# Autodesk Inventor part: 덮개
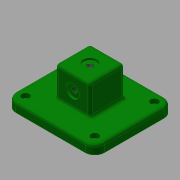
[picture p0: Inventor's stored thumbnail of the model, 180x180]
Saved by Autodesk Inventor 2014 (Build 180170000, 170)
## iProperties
Created: 2017-08
Part Number: 덮개
Material: 알루미늄 6061
Document SubType Name: Modeling
Designer: mduedu
Density: 1 g/cm^3
Appearance: Dark Green
Author: mduedu
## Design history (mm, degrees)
sketch "스케치1"
  geometry: L1 (46, -41)-(-46, -41); L2 (-46, -41)-(-46, 41); L3 (-46, 41)-(46, 41); L4 (46, 41)-(46, -41); 1 further point
  constraints: 8 end point, 2 parallel, 1 horizontal, 1 perpendicular
  dimensions: "d0" = 92 distance of L2.end L3.end; "d2" = 82 distance of L1.end L2.end; "d3" = 41 distance from line of L3 point (0, 0) (= 0.5 x d2); "d4" = 46 distance from line of point (0, 0) L4 (= 0.5 x d0)
extrude "돌출1" new body sketch "스케치1" distance "d5" = 10; taper "d6" = 0 deg
sketch "스케치2"
  geometry: L1 (-18, -18)-(18, -18); L2 (18, -18)-(18, 18); L3 (18, 18)-(-18, 18); L4 (-18, 18)-(-18, -18); L5 (-18, -18)-(18, 18); L6 (18, -18)-(-18, 18); 1 further point
  constraints: 12 end point, 2 midpoint, 2 parallel, 2 perpendicular, 1 horizontal
  dimensions: "d7" = 36 distance of L2.end L3.end
extrude "돌출2" join sketch "스케치2" distance "d9" = 32; taper "d10" = 0 deg
sketch "스케치3"
  geometry: L1 (-26, -26)-(26, -26); L2 (26, -26)-(26, 26); L3 (26, 26)-(-26, 26); L4 (-26, 26)-(-26, -26); L5 (-26, -26)-(26, 26); L6 (26, -26)-(-26, 26); 1 further point
  constraints: 12 end point, 2 midpoint, 2 parallel, 2 perpendicular, 1 horizontal
  dimensions: "d11" = 52 distance of L3.end L2.end
extrude "돌출3" join sketch "스케치3" distance "d12" = 6; taper "d13" = 0 deg
sketch "스케치4"
  geometry: L1 (-17, -17)-(17, -17); L2 (17, -17)-(17, 17); L3 (17, 17)-(-17, 17); L4 (-17, 17)-(-17, -17); L5 (-17, -17)-(17, 17); L6 (17, -17)-(-17, 17); 1 further point
  constraints: 12 end point, 2 midpoint, 2 parallel, 2 perpendicular, 1 horizontal
  dimensions: "d14" = 34 distance of L2.end L3.end
extrude "돌출4" cut sketch "스케치4" distance "d16" = 5; taper "d17" = 0 deg
sketch "스케치5"
  geometry: C1 r 9 at (0, 0); 1 further point
  constraints: 1 centre point, 1 coincident
  dimensions: "d18" = 18 diameter of C1
extrude "돌출5" cut sketch "스케치5" distance "d19" = 34; taper "d20" = 0 deg
sketch "스케치6"
  geometry: 2 further points
  constraints: 1 coincident
hole "구멍1" sketch "스케치6" at (0, 0) diameter "d21" = 5.917; stored, may be unused: countersink angle "d25" = 90 deg, drill point angle "d27" = 118 deg; dims "d22" = 6, "d23" = 14, "d24" = 2, "d26" = 8
sketch "스케치7"
  geometry: L1 (-28, -10)-(64, -10) reference; 3 further points
  constraints: 1 midpoint, 1 vertical alignment
  dimensions: "d47" = 26 distance from line of point (18, 16) L1
hole "구멍2" sketch "스케치7" at (18, 16) diameter "d29" = 5.917; stored, may be unused: countersink angle "d33" = 90 deg, drill point angle "d35" = 118 deg; dims "d30" = 6, "d31" = 14, "d32" = 2, "d34" = 8
fillet "모깎기1" dims "d36" = 10
fillet "모깎기2" dims "d37" = 3
fillet "모깎기3" dims "d38" = 3
fillet "모깎기4" dims "d39" = 3
fillet "모깎기5" dims "d40" = 3
chamfer "모따기1" distance "d41" = 1; stored, may be unused: second distance "d42" = 2, angle "d43" = 45 deg
fillet "모깎기6" dims "d44" = 3
fillet "모깎기7" dims "d45" = 3
fillet "모깎기8" dims "d46" = 3
sketch "스케치8"
  geometry: A1 r 10 centre (-36, -31) between (-46, -31) and (-36, -41) reference; A2 r 10 centre (-36, 31) between (-36, 41) and (-46, 31) reference; A3 r 10 centre (36, 31) between (46, 31) and (36, 41) reference; A4 r 10 centre (36, -31) between (36, -41) and (46, -31) reference; 5 further points
  constraints: 4 coincident
sketch "스케치9"
  geometry: 4 further points
  constraints: 4 other
hole "구멍3" sketch "스케치9" at (-36, -31), (-36, 31), (36, 31), (36, -31) diameter "d48" = 4.5; stored, may be unused: countersink angle "d52" = 90 deg, drill point angle "d54" = 0 deg; dims "d49" = 6, "d50" = 8, "d51" = 4.6, "d53" = 8
node "솔리드1"
